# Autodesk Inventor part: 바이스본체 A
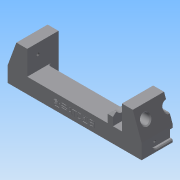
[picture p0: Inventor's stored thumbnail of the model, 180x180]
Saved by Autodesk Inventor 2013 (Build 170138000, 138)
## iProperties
Created: 2017-04
Part Number: 바이스본체 A
Material: 알루미늄 6061
Document SubType Name: Modeling
Designer: mduedu
Density: 2.71 g/cm^3
Mass: 246.801 g
Surface Area: 212.061 cm^2
Volume: 91.0705 cm^3
Author: mduedu
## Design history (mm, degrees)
sketch "스케치1"
  geometry: L1 (-75, 0)-(75, 0); L2 (-75, 0)-(-75, 17); L3 (-53, 17)-(53, 17); L4 (75, 17)-(75, 0); L5 (-75, 17)-(-65.173, 44); L6 (-65.173, 44)-(-53, 44); L7 (-53, 44)-(-53, 17); L8 (0, 0)-(0, 17); L9 (75, 17)-(65.173, 44); L10 (65.173, 44)-(53, 44); L11 (53, 44)-(53, 17); 1 further point
  constraints: 22 end point, 4 perpendicular, 2 horizontal alignment, 2 midpoint, 2 symmetric about line, 1 coincident, 1 collinear, 1 horizontal, 1 vertical
  dimensions: "d0" = 150 distance of L1.start L1.end; "d1" = 17 distance of L1.start L2.end; "d2" = 27 distance of L3.start L6.end; "d3" = 22 distance of L3.start L2.end; "d4" = 70 deg angle of L3 L5; "d54" = 20 deg angle of L9 L4
extrude "돌출1" new body sketch "스케치1" stored distance "d5" = 70; taper "d6" = 0 deg
sketch "스케치2"
  geometry: L1 (0, 70)-(106, 70) reference; L2 (106, 70)-(106, 0) reference; L3 (106, 0)-(0, 0) reference; L4 (0, 47)-(106, 47); L5 (106, 47)-(106, 23); L6 (106, 23)-(0, 23); L7 (0, 23)-(0, 47); L8 (0, 70)-(0, 0) reference; 2 further points
  constraints: 8 end point, 2 parallel, 2 point on line, 1 horizontal, 1 horizontal alignment, 1 midpoint, 1 perpendicular
  dimensions: "d7" = 24 distance between parallel lines of L6 L4
extrude "돌출2" cut sketch "스케치2" stored distance "d9" = 70; taper "d10" = 0 deg
sketch "스케치3"
  geometry: L1 (22, -23)-(128, -23) reference; L2 (128, -47)-(22, -47) reference; L3 (22, -18)-(128, -18); L4 (128, -52)-(22, -52); L5 (22, -18)-(22, -52); L6 (128, -18)-(128, -52); 1 further point
  constraints: 8 end point, 3 parallel, 2 point on line, 1 perpendicular
  dimensions: "d11" = 5 distance between parallel lines of L3 L1; "d12" = 5 distance between parallel lines of L4 L2
extrude "돌출3" cut sketch "스케치3" distance "d13" = 12; taper "d14" = 0 deg
fillet "모깎기1" dims "d15" = 3, "d16" = 3
sketch "스케치4"
  geometry: L1 (103, 23)-(3, 23) reference; L2 (0, 26)-(0, 0) reference; L3 (106, 0)-(0, 0) reference; L4 (106, 26)-(106, 0) reference; L5 (96, 0)-(90, 0); L6 (90, 0)-(90, 19.5); L7 (96, 19.5)-(96, 0); L8 (90, 19.5)-(96, 19.5); A1 r 3 centre (3, 26) between (0, 26) and (3, 23) reference; A2 r 3 centre (103, 26) between (103, 23) and (106, 26) reference; 1 further point
  constraints: 8 end point, 2 perpendicular, 1 horizontal, 1 parallel, 1 point on line
  dimensions: "d17" = 10 distance between parallel lines of L7 L4; "d18" = 6 distance between parallel lines of L7 L6; "d27" = 3.5 distance between parallel lines of L8 L1
extrude "돌출4" join sketch "스케치4" distance "d19" = 12; taper "d20" = 0 deg
chamfer "모따기1" distance "d21" = 3; stored, may be unused: second distance "d22" = 2, angle "d23" = 45 deg
chamfer "모따기2" distance "d24" = 3; stored, may be unused: second distance "d25" = 2, angle "d26" = 45 deg
sketch "스케치5"
  geometry: L1 (-15.5, 35.8)-(-15.5, -25.8) reference; L2 (19.5, 0)-(0, 0) reference; C1 r 6.5 at (9.5, 15); 1 further point
  constraints: 1 centre point
  dimensions: "d28" = 13 diameter of C1; "d30" = 15 distance from line of C1.centre L2; "d31" = 25 distance from line of C1.centre L1
extrude "돌출5" cut sketch "스케치5" stored distance "d32" = 12; taper "d33" = 0 deg
sketch "스케치6"
  geometry: C1 r 5 at (-10, 15); C2 r 5 at (-60, 15); A1 r 6.5 centre (-10, 15) between (-15.766, 12) and (-4.234, 12) reference; A2 r 6.5 centre (-60, 15) between (-65.766, 12) and (-54.234, 12) reference; 1 further point
  constraints: 2 centre point, 2 coincident
  dimensions: "d34" = 10 diameter of C1; "d35" = 10 diameter of C2 (= d34)
extrude "돌출6" cut sketch "스케치6" stored distance "d36" = 12; taper "d37" = 0 deg
chamfer "모따기3" distance "d38" = 1; stored, may be unused: second distance "d39" = 2, angle "d40" = 45 deg
chamfer "모따기4" distance "d41" = 1; stored, may be unused: second distance "d42" = 2, angle "d43" = 45 deg
sketch "스케치7"
  geometry: L1 (-35, 35.8)-(-35, -25.8) reference; L2 (-70, 0)-(0, 0) reference; C1 r 5 at (-35, 15); 1 further point
  constraints: 1 centre point, 1 point on line
  dimensions: "d44" = 10 diameter of C1; "d45" = 15 distance from line of C1.centre L2
extrude "돌출7" cut sketch "스케치7" stored distance "d46" = 12; taper "d47" = 0 deg
chamfer "모따기5" distance "d48" = 1; stored, may be unused: second distance "d49" = 2, angle "d50" = 45 deg
node "작업축1"
sketch "스케치8"
  geometry: L1 (-105, 32)-(105, 32) reference; L2 (58, 32)-(64, 32); L3 (64, 32)-(64, 40); L4 (64, 40)-(58, 40); L5 (58, 40)-(58, 32); L6 (53, 38)-(53, 26) reference; 1 further point
  constraints: 8 end point, 2 parallel, 1 horizontal, 1 perpendicular, 1 point on line
  dimensions: "d51" = 5 distance from line of L6 L2.start; "d52" = 6 distance of L3.end L4.end; "d53" = 16 diameter of L4 L1
revolve "회전1" sketch "스케치8" stored, may be unused: angle "d55" = 90 deg
fillet "모깎기2"
chamfer "모따기6" distance "d56" = 1; stored, may be unused: second distance "d57" = 2, angle "d58" = 45 deg
sketch "스케치9"
  geometry: L1 (17.5, 3)-(52.5, 3); L2 (52.5, 13)-(17.5, 13); L3 (70, 0)-(0, 0) reference; L4 (17.5, 8)-(52.5, 8); A1 r 5 centre (17.5, 8) between (17.5, 13) and (17.5, 3); A2 r 5 centre (52.5, 8) between (52.5, 3) and (52.5, 13); 3 further points
  constraints: 6 end point, 4 point on circle, 3 tangent, 2 centre point, 2 midpoint, 2 parallel, 1 horizontal, 1 vertical alignment
  dimensions: "d59" = 35 distance of L4.start L4.end; "d61" = 5 radius of A2; "d62" = 8 distance between parallel lines of L3 L4
extrude "돌출8" cut sketch "스케치9" distance "d63" = 3; taper "d64" = 0 deg
chamfer "모따기7" distance "d65" = 1; stored, may be unused: second distance "d66" = 2, angle "d67" = 45 deg
chamfer "모따기8" distance "d68" = 1; stored, may be unused: second distance "d69" = 2, angle "d70" = 45 deg
feature "분할1"
sketch "스케치10"
  geometry: L1 (35, 27)-(0, 27) reference; L2 (0, 0)-(0, 27) reference; 1 further point
  dimensions: "d85" = 11.5 distance from line of point (12, 15.5) L1; "d86" = 12 distance from line of point (12, 15.5) L2
hole "구멍1" sketch "스케치10" at (12, 15.5) diameter "d71" = 3.242; stored, may be unused: countersink angle "d75" = 90 deg, drill point angle "d77" = 120 deg; dims "d72" = 6, "d73" = 4, "d74" = 2, "d76" = 8
sketch "스케치11"
  geometry: A1 r 5 centre (17.5, 8) between (17.5, 13) and (17.5, 3) reference; 1 further point
  constraints: 1 coincident
hole "구멍3" sketch "스케치11" at (17.5, 8) diameter "d78" = 2.459; stored, may be unused: countersink angle "d82" = 90 deg, drill point angle "d84" = 120 deg; dims "d79" = 4.5, "d80" = 4, "d81" = 2, "d83" = 6
sketch "스케치12"
  geometry: L1 (-75, 0)-(75, 0) reference; 3 further points
  constraints: 1 midpoint, 1 vertical alignment, 1 other
  dimensions: "d87" = 8 distance of point (0, 8) point (0, 0)
feature "엠보싱1" sketch "스케치12" dims "d7" = 24, "d88" = 0.5, "d89" = 0
node "솔리드1"
mirror "대칭1"
mirror "대칭2"
mirror "대칭3"
mirror "대칭4"
node "투영된 루프1"
